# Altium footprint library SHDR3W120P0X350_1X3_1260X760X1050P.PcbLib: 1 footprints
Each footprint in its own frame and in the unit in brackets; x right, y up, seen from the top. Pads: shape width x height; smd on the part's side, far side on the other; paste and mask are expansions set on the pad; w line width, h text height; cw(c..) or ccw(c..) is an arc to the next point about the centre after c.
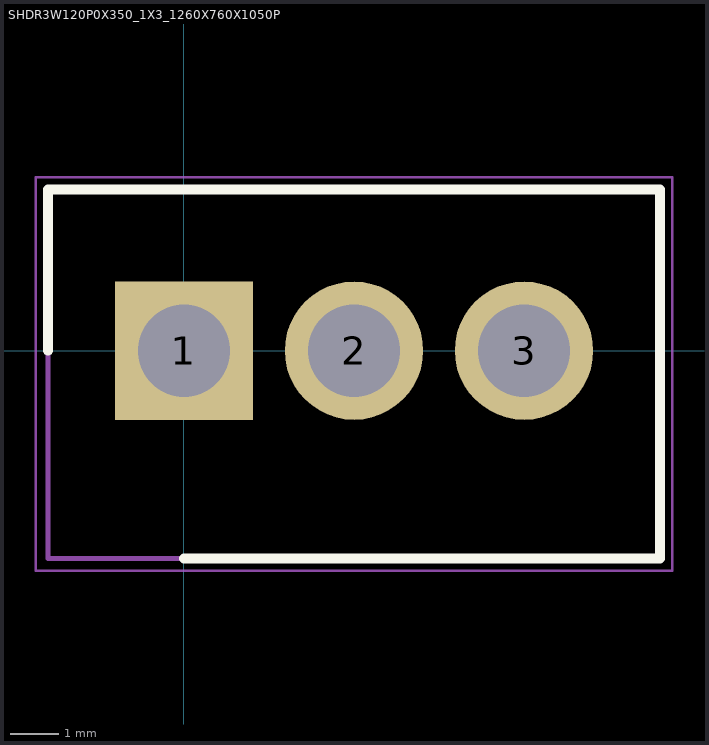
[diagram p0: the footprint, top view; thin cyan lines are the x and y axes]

## SHDR3W120P0X350_1X3_1260X760X1050P [mm]
pads (3):
  rect 2.85x2.85 / inner round 2.85 / far side rect 2.85x2.85 hole 1.9: 1(0,0)
  round 2.85 hole 1.9: 2(3.5,0) 3(7,0)
Top Overlay:
  lines w0.2: -2.8,0 -2.8,3.32 9.8,3.32 9.8,-4.28 0,-4.28
Mechanical 15:
  lines w0.1: -2.8,-4.28 -2.8,3.32 9.8,3.32 9.8,-4.28 -2.8,-4.28
Mechanical 20:
  lines w0.05: -3.05,-4.53 -3.05,3.57 10.05,3.57 10.05,-4.53 -3.05,-4.53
